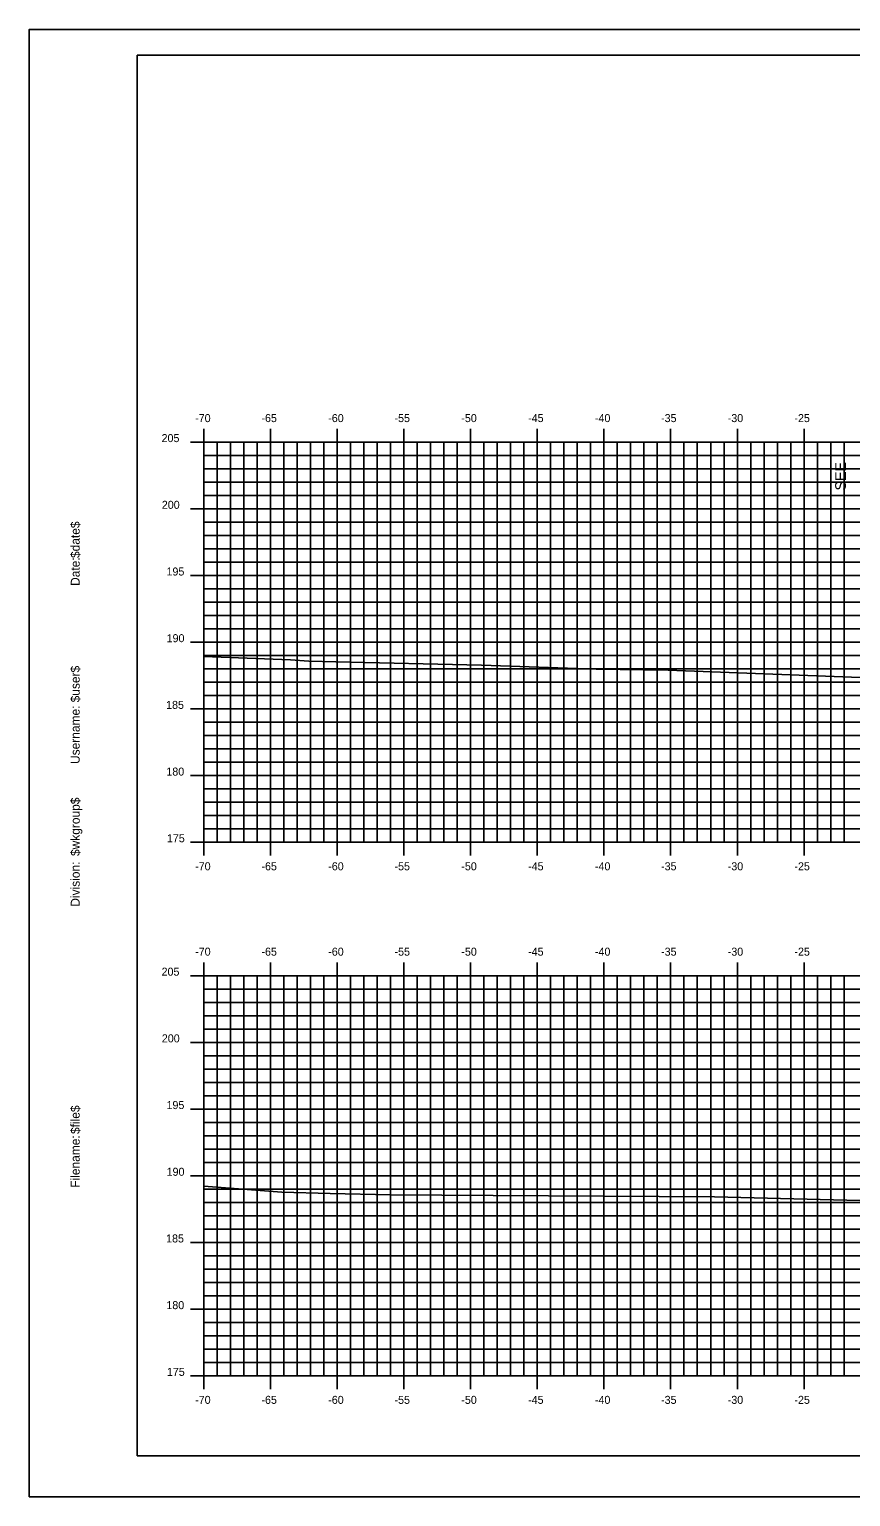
# Model space of a CAD drawing. Extents: x 1723740 to 1723911, y 459560 to 459670.
# Drawn here: x 1723739.6 to 1723801.2, y 459559.6 to 459669.6 of the extents above; entities that cross this region are included whole.
import ezdxf

# ---------------------------------------------------------------- set-up
doc = ezdxf.new("R2010")
doc.units = 0
for name, color, linetype in [('ANNOTATION', 7, 'Continuous'), ('BORDER', 7, 'Continuous'), ('H_V ANNOTATION', 7, 'Continuous'), ('MAJOR', 7, 'Continuous'), ('MINOR', 7, 'Continuous'), ('PLOT BOUNDARY', 7, 'Continuous'), ('S_Roadway_Centerline', 7, 'Continuous')]:
    doc.layers.add(name, color=color, linetype=linetype)

msp = doc.modelspace()

# ---------------------------------------------------------------- linework, layer by layer
at = {"layer": 'BORDER'}
msp.add_lwpolyline([(1723747.72, 459562.61), (1723907.72, 459562.61), (1723907.72, 459667.61), (1723747.72, 459667.61)], close=True, dxfattribs=at)
at = {"layer": 'MAJOR'}
for p, q in [((1723752.72, 459639.61), (1723752.72, 459638.61)), ((1723757.72, 459639.61), (1723757.72, 459638.61)), ((1723762.72, 459639.61), (1723762.72, 459638.61)), ((1723767.72, 459639.61), (1723767.72, 459638.61)), ((1723772.72, 459639.61), (1723772.72, 459638.61)), ((1723777.72, 459639.61), (1723777.72, 459638.61)), ((1723782.72, 459639.61), (1723782.72, 459638.61)), ((1723787.72, 459639.61), (1723787.72, 459638.61)), ((1723792.72, 459639.61), (1723792.72, 459638.61)), ((1723797.72, 459639.61), (1723797.72, 459638.61)), ((1723751.71, 459638.61), (1723752.72, 459638.61)), ((1723752.72, 459638.61), (1723892.72, 459638.61)), ((1723752.72, 459608.61), (1723752.72, 459638.61)), ((1723752.72, 459608.61), (1723752.72, 459638.61)), ((1723752.72, 459638.61), (1723892.72, 459638.61)), ((1723757.72, 459608.61), (1723757.72, 459638.61)), ((1723762.72, 459608.61), (1723762.72, 459638.61)), ((1723767.72, 459608.61), (1723767.72, 459638.61)), ((1723772.72, 459608.61), (1723772.72, 459638.61)), ((1723777.72, 459608.61), (1723777.72, 459638.61)), ((1723782.72, 459608.61), (1723782.72, 459638.61)), ((1723787.72, 459608.61), (1723787.72, 459638.61)), ((1723792.72, 459608.61), (1723792.72, 459638.61)), ((1723797.72, 459608.61), (1723797.72, 459638.61)), ((1723751.71, 459633.61), (1723752.72, 459633.61)), ((1723752.72, 459633.61), (1723892.72, 459633.61)), ((1723751.71, 459628.61), (1723752.72, 459628.61)), ((1723752.72, 459628.61), (1723892.72, 459628.61)), ((1723751.71, 459623.61), (1723752.72, 459623.61)), ((1723752.72, 459623.61), (1723892.72, 459623.61)), ((1723751.71, 459618.61), (1723752.72, 459618.61)), ((1723752.72, 459618.61), (1723892.72, 459618.61)), ((1723751.71, 459613.61), (1723752.72, 459613.61)), ((1723752.72, 459613.61), (1723892.72, 459613.61)), ((1723751.71, 459608.61), (1723752.72, 459608.61)), ((1723752.72, 459608.61), (1723892.72, 459608.61)), ((1723752.72, 459608.61), (1723892.72, 459608.61)), ((1723752.72, 459607.61), (1723752.72, 459608.61)), ((1723757.72, 459607.61), (1723757.72, 459608.61)), ((1723762.72, 459607.61), (1723762.72, 459608.61)), ((1723767.72, 459607.61), (1723767.72, 459608.61)), ((1723772.72, 459607.61), (1723772.72, 459608.61)), ((1723777.72, 459607.61), (1723777.72, 459608.61)), ((1723782.72, 459607.61), (1723782.72, 459608.61)), ((1723787.72, 459607.61), (1723787.72, 459608.61)), ((1723792.72, 459607.61), (1723792.72, 459608.61)), ((1723797.72, 459607.61), (1723797.72, 459608.61)), ((1723752.72, 459599.61), (1723752.72, 459598.61)), ((1723757.72, 459599.61), (1723757.72, 459598.61)), ((1723762.72, 459599.61), (1723762.72, 459598.61)), ((1723767.72, 459599.61), (1723767.72, 459598.61)), ((1723772.72, 459599.61), (1723772.72, 459598.61)), ((1723777.72, 459599.61), (1723777.72, 459598.61)), ((1723782.72, 459599.61), (1723782.72, 459598.61)), ((1723787.72, 459599.61), (1723787.72, 459598.61)), ((1723792.72, 459599.61), (1723792.72, 459598.61)), ((1723797.72, 459599.61), (1723797.72, 459598.61)), ((1723751.71, 459598.61), (1723752.72, 459598.61)), ((1723752.72, 459598.61), (1723892.72, 459598.61)), ((1723752.72, 459568.61), (1723752.72, 459598.61)), ((1723752.72, 459568.61), (1723752.72, 459598.61)), ((1723752.72, 459598.61), (1723892.72, 459598.61)), ((1723757.72, 459568.61), (1723757.72, 459598.61)), ((1723762.72, 459568.61), (1723762.72, 459598.61)), ((1723767.72, 459568.61), (1723767.72, 459598.61)), ((1723772.72, 459568.61), (1723772.72, 459598.61)), ((1723777.72, 459568.61), (1723777.72, 459598.61)), ((1723782.72, 459568.61), (1723782.72, 459598.61)), ((1723787.72, 459568.61), (1723787.72, 459598.61)), ((1723792.72, 459568.61), (1723792.72, 459598.61)), ((1723797.72, 459568.61), (1723797.72, 459598.61)), ((1723751.71, 459593.61), (1723752.72, 459593.61)), ((1723752.72, 459593.61), (1723892.72, 459593.61)), ((1723751.71, 459588.61), (1723752.72, 459588.61)), ((1723752.72, 459588.61), (1723892.72, 459588.61)), ((1723751.71, 459583.61), (1723752.72, 459583.61)), ((1723752.72, 459583.61), (1723892.72, 459583.61)), ((1723751.71, 459578.61), (1723752.72, 459578.61)), ((1723752.72, 459578.61), (1723892.72, 459578.61)), ((1723751.71, 459573.61), (1723752.72, 459573.61)), ((1723752.72, 459573.61), (1723892.72, 459573.61)), ((1723751.71, 459568.61), (1723752.72, 459568.61)), ((1723752.72, 459568.61), (1723892.72, 459568.61)), ((1723752.72, 459568.61), (1723892.72, 459568.61)), ((1723752.72, 459567.61), (1723752.72, 459568.61)), ((1723757.72, 459567.61), (1723757.72, 459568.61)), ((1723762.72, 459567.61), (1723762.72, 459568.61)), ((1723767.72, 459567.61), (1723767.72, 459568.61)), ((1723772.72, 459567.61), (1723772.72, 459568.61)), ((1723777.72, 459567.61), (1723777.72, 459568.61)), ((1723782.72, 459567.61), (1723782.72, 459568.61)), ((1723787.72, 459567.61), (1723787.72, 459568.61)), ((1723792.72, 459567.61), (1723792.72, 459568.61)), ((1723797.72, 459567.61), (1723797.72, 459568.61))]:
    msp.add_line(p, q, dxfattribs=at)
at = {"layer": 'MINOR'}
for p, q in [((1723753.72, 459608.61), (1723753.72, 459638.61)), ((1723754.72, 459608.61), (1723754.72, 459638.61)), ((1723755.72, 459608.61), (1723755.72, 459638.61)), ((1723756.72, 459608.61), (1723756.72, 459638.61)), ((1723758.72, 459608.61), (1723758.72, 459638.61)), ((1723759.72, 459608.61), (1723759.72, 459638.61)), ((1723760.72, 459608.61), (1723760.72, 459638.61)), ((1723761.72, 459608.61), (1723761.72, 459638.61)), ((1723763.72, 459608.61), (1723763.72, 459638.61)), ((1723764.72, 459608.61), (1723764.72, 459638.61)), ((1723765.72, 459608.61), (1723765.72, 459638.61)), ((1723766.72, 459608.61), (1723766.72, 459638.61)), ((1723768.72, 459608.61), (1723768.72, 459638.61)), ((1723769.72, 459608.61), (1723769.72, 459638.61)), ((1723770.72, 459608.61), (1723770.72, 459638.61)), ((1723771.72, 459608.61), (1723771.72, 459638.61)), ((1723773.72, 459608.61), (1723773.72, 459638.61)), ((1723774.72, 459608.61), (1723774.72, 459638.61)), ((1723775.72, 459608.61), (1723775.72, 459638.61)), ((1723776.72, 459608.61), (1723776.72, 459638.61)), ((1723778.72, 459608.61), (1723778.72, 459638.61)), ((1723779.72, 459608.61), (1723779.72, 459638.61)), ((1723780.72, 459608.61), (1723780.72, 459638.61)), ((1723781.72, 459608.61), (1723781.72, 459638.61)), ((1723783.72, 459608.61), (1723783.72, 459638.61)), ((1723784.72, 459608.61), (1723784.72, 459638.61)), ((1723785.72, 459608.61), (1723785.72, 459638.61)), ((1723786.72, 459608.61), (1723786.72, 459638.61)), ((1723788.72, 459608.61), (1723788.72, 459638.61)), ((1723789.72, 459608.61), (1723789.72, 459638.61)), ((1723790.72, 459608.61), (1723790.72, 459638.61)), ((1723791.72, 459608.61), (1723791.72, 459638.61)), ((1723793.72, 459608.61), (1723793.72, 459638.61)), ((1723794.72, 459608.61), (1723794.72, 459638.61)), ((1723795.72, 459608.61), (1723795.72, 459638.61)), ((1723796.72, 459608.61), (1723796.72, 459638.61)), ((1723798.72, 459608.61), (1723798.72, 459638.61)), ((1723799.72, 459608.61), (1723799.72, 459638.61)), ((1723800.72, 459608.61), (1723800.72, 459638.61)), ((1723752.72, 459637.61), (1723892.72, 459637.61)), ((1723752.72, 459637.61), (1723753.72, 459637.61)), ((1723752.72, 459636.61), (1723892.72, 459636.61)), ((1723752.72, 459636.61), (1723753.72, 459636.61)), ((1723752.72, 459635.61), (1723892.72, 459635.61)), ((1723752.72, 459635.61), (1723753.72, 459635.61)), ((1723752.72, 459634.61), (1723892.72, 459634.61)), ((1723752.72, 459634.61), (1723753.72, 459634.61)), ((1723752.72, 459632.61), (1723892.72, 459632.61)), ((1723752.72, 459632.61), (1723753.72, 459632.61)), ((1723752.72, 459631.61), (1723892.72, 459631.61)), ((1723752.72, 459631.61), (1723753.72, 459631.61)), ((1723752.72, 459630.61), (1723892.72, 459630.61)), ((1723752.72, 459630.61), (1723753.72, 459630.61)), ((1723752.72, 459629.61), (1723892.72, 459629.61)), ((1723752.72, 459629.61), (1723753.72, 459629.61)), ((1723752.72, 459627.61), (1723892.72, 459627.61)), ((1723752.72, 459627.61), (1723753.72, 459627.61)), ((1723752.72, 459626.61), (1723892.72, 459626.61)), ((1723752.72, 459626.61), (1723753.72, 459626.61)), ((1723752.72, 459625.61), (1723892.72, 459625.61)), ((1723752.72, 459625.61), (1723753.72, 459625.61)), ((1723752.72, 459624.61), (1723892.72, 459624.61)), ((1723752.72, 459624.61), (1723753.72, 459624.61)), ((1723752.72, 459622.61), (1723892.72, 459622.61)), ((1723752.72, 459622.61), (1723753.72, 459622.61)), ((1723752.72, 459621.61), (1723892.72, 459621.61)), ((1723752.72, 459621.61), (1723753.72, 459621.61)), ((1723752.72, 459620.61), (1723892.72, 459620.61)), ((1723752.72, 459620.61), (1723753.72, 459620.61)), ((1723752.72, 459619.61), (1723892.72, 459619.61)), ((1723752.72, 459619.61), (1723753.72, 459619.61)), ((1723752.72, 459617.61), (1723892.72, 459617.61)), ((1723752.72, 459617.61), (1723753.72, 459617.61)), ((1723752.72, 459616.61), (1723892.72, 459616.61)), ((1723752.72, 459616.61), (1723753.72, 459616.61)), ((1723752.72, 459615.61), (1723892.72, 459615.61)), ((1723752.72, 459615.61), (1723753.72, 459615.61)), ((1723752.72, 459614.61), (1723892.72, 459614.61)), ((1723752.72, 459614.61), (1723753.72, 459614.61)), ((1723752.72, 459612.61), (1723892.72, 459612.61)), ((1723752.72, 459612.61), (1723753.72, 459612.61)), ((1723752.72, 459611.61), (1723892.72, 459611.61)), ((1723752.72, 459611.61), (1723753.72, 459611.61)), ((1723752.72, 459610.61), (1723892.72, 459610.61)), ((1723752.72, 459610.61), (1723753.72, 459610.61)), ((1723752.72, 459609.61), (1723892.72, 459609.61)), ((1723752.72, 459609.61), (1723753.72, 459609.61)), ((1723752.72, 459597.61), (1723892.72, 459597.61)), ((1723752.72, 459597.61), (1723753.72, 459597.61)), ((1723753.72, 459568.61), (1723753.72, 459598.61)), ((1723754.72, 459568.61), (1723754.72, 459598.61)), ((1723755.72, 459568.61), (1723755.72, 459598.61)), ((1723756.72, 459568.61), (1723756.72, 459598.61)), ((1723758.72, 459568.61), (1723758.72, 459598.61)), ((1723759.72, 459568.61), (1723759.72, 459598.61)), ((1723760.72, 459568.61), (1723760.72, 459598.61)), ((1723761.72, 459568.61), (1723761.72, 459598.61)), ((1723763.72, 459568.61), (1723763.72, 459598.61)), ((1723764.72, 459568.61), (1723764.72, 459598.61)), ((1723765.72, 459568.61), (1723765.72, 459598.61)), ((1723766.72, 459568.61), (1723766.72, 459598.61)), ((1723768.72, 459568.61), (1723768.72, 459598.61)), ((1723769.72, 459568.61), (1723769.72, 459598.61)), ((1723770.72, 459568.61), (1723770.72, 459598.61)), ((1723771.72, 459568.61), (1723771.72, 459598.61)), ((1723773.72, 459568.61), (1723773.72, 459598.61)), ((1723774.72, 459568.61), (1723774.72, 459598.61)), ((1723775.72, 459568.61), (1723775.72, 459598.61)), ((1723776.72, 459568.61), (1723776.72, 459598.61)), ((1723778.72, 459568.61), (1723778.72, 459598.61)), ((1723779.72, 459568.61), (1723779.72, 459598.61)), ((1723780.72, 459568.61), (1723780.72, 459598.61)), ((1723781.72, 459568.61), (1723781.72, 459598.61)), ((1723783.72, 459568.61), (1723783.72, 459598.61)), ((1723784.72, 459568.61), (1723784.72, 459598.61)), ((1723785.72, 459568.61), (1723785.72, 459598.61)), ((1723786.72, 459568.61), (1723786.72, 459598.61)), ((1723788.72, 459568.61), (1723788.72, 459598.61)), ((1723789.72, 459568.61), (1723789.72, 459598.61)), ((1723790.72, 459568.61), (1723790.72, 459598.61)), ((1723791.72, 459568.61), (1723791.72, 459598.61)), ((1723793.72, 459568.61), (1723793.72, 459598.61)), ((1723794.72, 459568.61), (1723794.72, 459598.61)), ((1723795.72, 459568.61), (1723795.72, 459598.61)), ((1723796.72, 459568.61), (1723796.72, 459598.61)), ((1723798.72, 459568.61), (1723798.72, 459598.61)), ((1723799.72, 459568.61), (1723799.72, 459598.61)), ((1723800.72, 459568.61), (1723800.72, 459598.61)), ((1723752.72, 459596.61), (1723892.72, 459596.61)), ((1723752.72, 459596.61), (1723753.72, 459596.61)), ((1723752.72, 459595.61), (1723892.72, 459595.61)), ((1723752.72, 459595.61), (1723753.72, 459595.61)), ((1723752.72, 459594.61), (1723892.72, 459594.61)), ((1723752.72, 459594.61), (1723753.72, 459594.61)), ((1723752.72, 459592.61), (1723892.72, 459592.61)), ((1723752.72, 459592.61), (1723753.72, 459592.61)), ((1723752.72, 459591.61), (1723892.72, 459591.61)), ((1723752.72, 459591.61), (1723753.72, 459591.61)), ((1723752.72, 459590.61), (1723892.72, 459590.61)), ((1723752.72, 459590.61), (1723753.72, 459590.61)), ((1723752.72, 459589.61), (1723892.72, 459589.61)), ((1723752.72, 459589.61), (1723753.72, 459589.61)), ((1723752.72, 459587.61), (1723892.72, 459587.61)), ((1723752.72, 459587.61), (1723753.72, 459587.61)), ((1723752.72, 459586.61), (1723892.72, 459586.61)), ((1723752.72, 459586.61), (1723753.72, 459586.61)), ((1723752.72, 459585.61), (1723892.72, 459585.61)), ((1723752.72, 459585.61), (1723753.72, 459585.61)), ((1723752.72, 459584.61), (1723892.72, 459584.61)), ((1723752.72, 459584.61), (1723753.72, 459584.61)), ((1723752.72, 459582.61), (1723892.72, 459582.61)), ((1723752.72, 459582.61), (1723753.72, 459582.61)), ((1723752.72, 459581.61), (1723892.72, 459581.61)), ((1723752.72, 459581.61), (1723753.72, 459581.61)), ((1723752.72, 459580.61), (1723892.72, 459580.61)), ((1723752.72, 459580.61), (1723753.72, 459580.61)), ((1723752.72, 459579.61), (1723892.72, 459579.61)), ((1723752.72, 459579.61), (1723753.72, 459579.61)), ((1723752.72, 459577.61), (1723892.72, 459577.61)), ((1723752.72, 459577.61), (1723753.72, 459577.61)), ((1723752.72, 459576.61), (1723892.72, 459576.61)), ((1723752.72, 459576.61), (1723753.72, 459576.61)), ((1723752.72, 459575.61), (1723892.72, 459575.61)), ((1723752.72, 459575.61), (1723753.72, 459575.61)), ((1723752.72, 459574.61), (1723892.72, 459574.61)), ((1723752.72, 459574.61), (1723753.72, 459574.61)), ((1723752.72, 459572.61), (1723892.72, 459572.61)), ((1723752.72, 459572.61), (1723753.72, 459572.61)), ((1723752.72, 459571.61), (1723892.72, 459571.61)), ((1723752.72, 459571.61), (1723753.72, 459571.61)), ((1723752.72, 459570.61), (1723892.72, 459570.61)), ((1723752.72, 459570.61), (1723753.72, 459570.61)), ((1723752.72, 459569.61), (1723892.72, 459569.61)), ((1723752.72, 459569.61), (1723753.72, 459569.61))]:
    msp.add_line(p, q, dxfattribs=at)
at = {"layer": 'PLOT BOUNDARY'}
msp.add_lwpolyline([(1723739.62, 459559.55), (1723909.62, 459559.55), (1723909.62, 459669.55), (1723739.62, 459669.55)], close=True, dxfattribs=at)
at = {"layer": 'S_Roadway_Centerline'}
for points in [[(1723752.72, 459622.54), (1723759.22, 459622.29), (1723760.58, 459622.19), (1723762.62, 459622.14), (1723773.54, 459621.89), (1723782.14, 459621.6), (1723787.53, 459621.52), (1723807.19, 459620.76), (1723811.22, 459620.55), (1723825.57, 459620.18), (1723836.05, 459620), (1723846.28, 459619.83), (1723860.82, 459619.16), (1723865.74, 459618.85), (1723869.67, 459618.76), (1723877.33, 459618.67), (1723886.57, 459618.54), (1723889.34, 459618.52), (1723891.65, 459618.48), (1723892.72, 459618.47)], [(1723752.72, 459582.84), (1723758.56, 459582.38), (1723762.18, 459582.27), (1723766.71, 459582.17), (1723774.4, 459582.14), (1723791, 459582.02), (1723802.91, 459581.73), (1723808.36, 459581.53), (1723813.88, 459581.43), (1723819.34, 459581.21), (1723825.09, 459580.85), (1723832.69, 459580.38), (1723841.04, 459580.51), (1723843.4, 459580.59), (1723845.73, 459580.48), (1723866.78, 459579.6), (1723868.76, 459579.54), (1723878.05, 459578.92), (1723890.34, 459578.54), (1723890.75, 459578.53), (1723892.72, 459578.43)]]:
    msp.add_lwpolyline(points, dxfattribs=at)

# ---------------------------------------------------------------- texts
at = {"layer": 'ANNOTATION'}
msp.add_text('SEE', height=0.8, rotation=90, dxfattribs=at).set_placement((1723800.86, 459634.98))
at = {"layer": 'BORDER'}
for s, p in [('$date$', (1723743.4, 459629.92)), ('Date:', (1723743.4, 459627.83)), ('$user$', (1723743.4, 459619.1)), ('Username:', (1723743.4, 459614.48)), ('$wkgroup$', (1723743.4, 459607.58)), ('Division:', (1723743.4, 459603.78)), ('$file$', (1723743.4, 459586.74)), ('Filename:', (1723743.4, 459582.71))]:
    msp.add_text(s, height=0.67, rotation=90, dxfattribs=at).set_placement(p)
at = {"layer": 'H_V ANNOTATION'}
for s, p in [('-70', (1723752.06, 459640.11)), ('-65', (1723757.03, 459640.11)), ('-60', (1723762.04, 459640.11)), ('-55', (1723767.01, 459640.11)), ('-50', (1723772.02, 459640.11)), ('-45', (1723777.03, 459640.11)), ('-40', (1723782.04, 459640.11)), ('-35', (1723787, 459640.11)), ('-30', (1723792, 459640.11)), ('-25', (1723797, 459640.11)), ('205', (1723749.54, 459638.61)), ('200', (1723749.56, 459633.61)), ('195', (1723749.91, 459628.61)), ('190', (1723749.92, 459623.61)), ('185', (1723749.88, 459618.61)), ('180', (1723749.9, 459613.61)), ('175', (1723749.94, 459608.61)), ('-70', (1723752.06, 459606.51)), ('-65', (1723757.03, 459606.51)), ('-60', (1723762.04, 459606.51)), ('-55', (1723767.01, 459606.51)), ('-50', (1723772.02, 459606.51)), ('-45', (1723777.03, 459606.51)), ('-40', (1723782.04, 459606.51)), ('-35', (1723787, 459606.51)), ('-30', (1723792, 459606.51)), ('-25', (1723797, 459606.51)), ('-70', (1723752.06, 459600.11)), ('-65', (1723757.03, 459600.11)), ('-60', (1723762.04, 459600.11)), ('-55', (1723767.01, 459600.11)), ('-50', (1723772.02, 459600.11)), ('-45', (1723777.03, 459600.11)), ('-40', (1723782.04, 459600.11)), ('-35', (1723787, 459600.11)), ('-30', (1723792, 459600.11)), ('-25', (1723797, 459600.11)), ('205', (1723749.54, 459598.61)), ('200', (1723749.56, 459593.61)), ('195', (1723749.91, 459588.61)), ('190', (1723749.92, 459583.61)), ('185', (1723749.88, 459578.61)), ('180', (1723749.9, 459573.61)), ('175', (1723749.94, 459568.61)), ('-70', (1723752.06, 459566.51)), ('-65', (1723757.03, 459566.51)), ('-60', (1723762.04, 459566.51)), ('-55', (1723767.01, 459566.51)), ('-50', (1723772.02, 459566.51)), ('-45', (1723777.03, 459566.51)), ('-40', (1723782.04, 459566.51)), ('-35', (1723787, 459566.51)), ('-30', (1723792, 459566.51)), ('-25', (1723797, 459566.51))]:
    msp.add_text(s, height=0.6, dxfattribs=at).set_placement(p)
at = {"layer": 'MAJOR'}
for p in [(1723752.71, 459608.61), (1723752.71, 459568.61)]:
    msp.add_text('-', height=0.006, dxfattribs=at).set_placement(p)

doc.saveas('drawing.dxf')
